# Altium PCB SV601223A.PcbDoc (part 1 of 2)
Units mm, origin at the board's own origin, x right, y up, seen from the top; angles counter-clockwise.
Board outline 162.56 x 88.9 mm, 2 copper layers (Top Layer, Bottom Layer), stack 1.554 mm thick; 111 components, 38 nets, 197 pads, 254 vias.
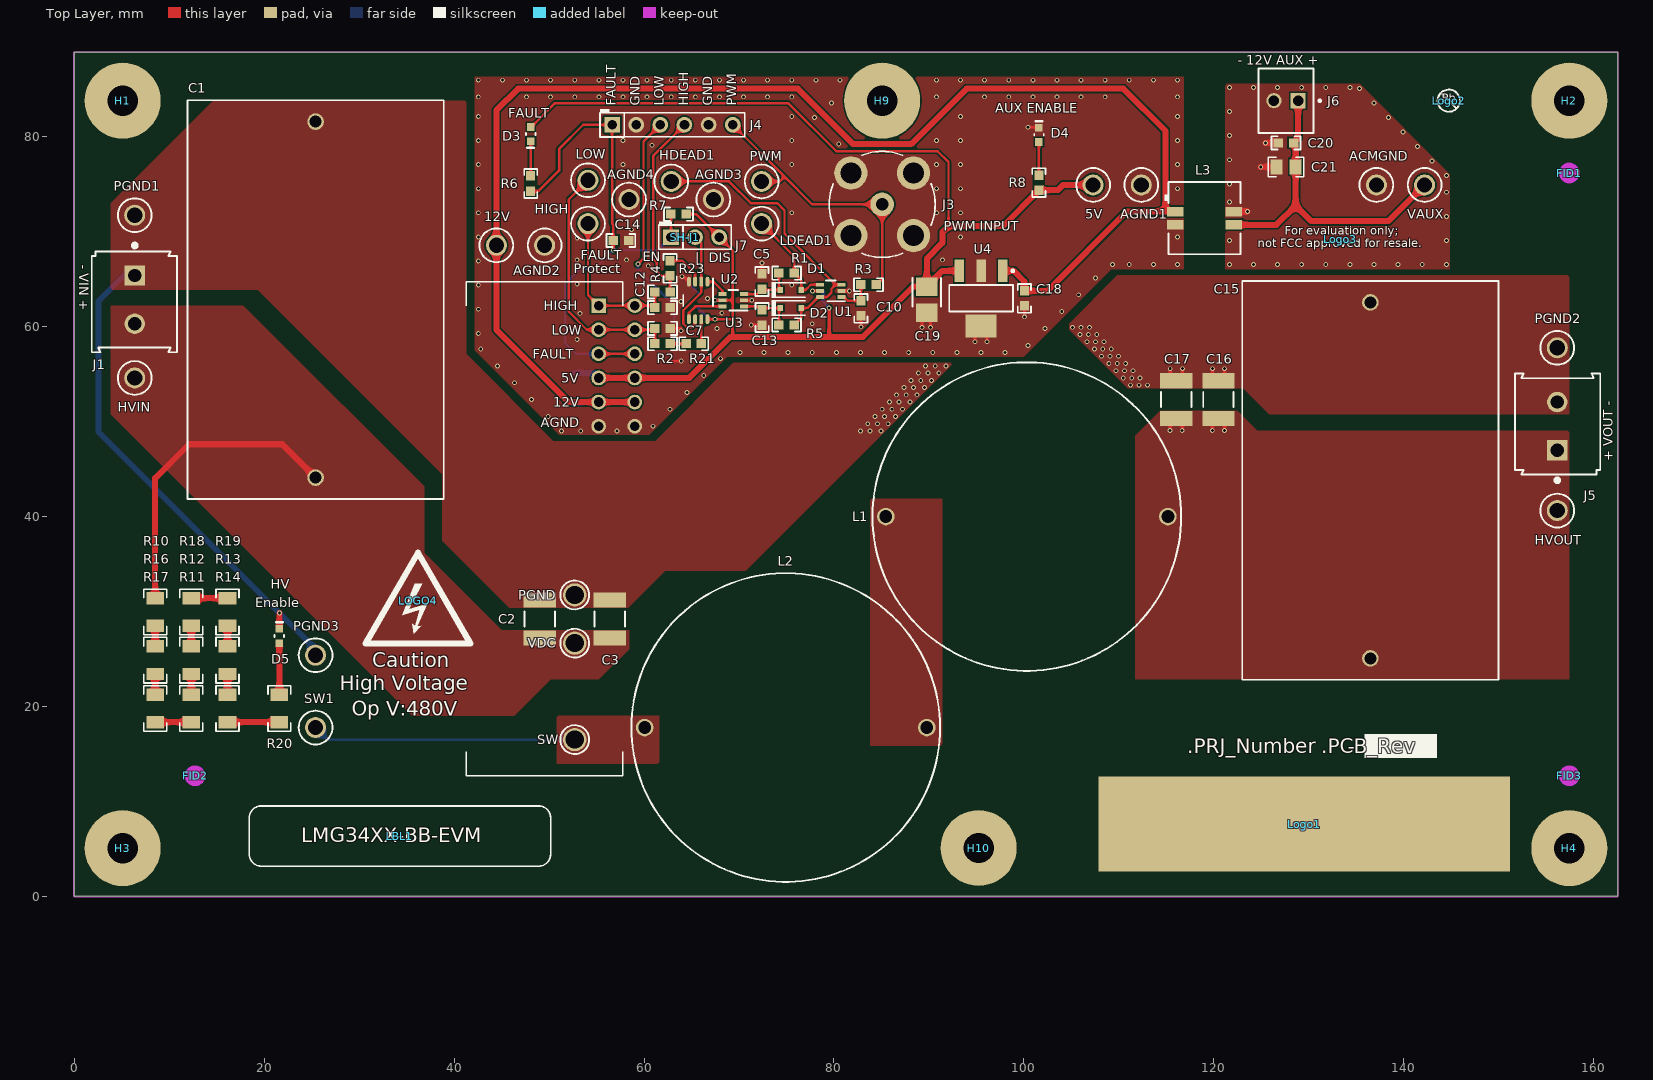
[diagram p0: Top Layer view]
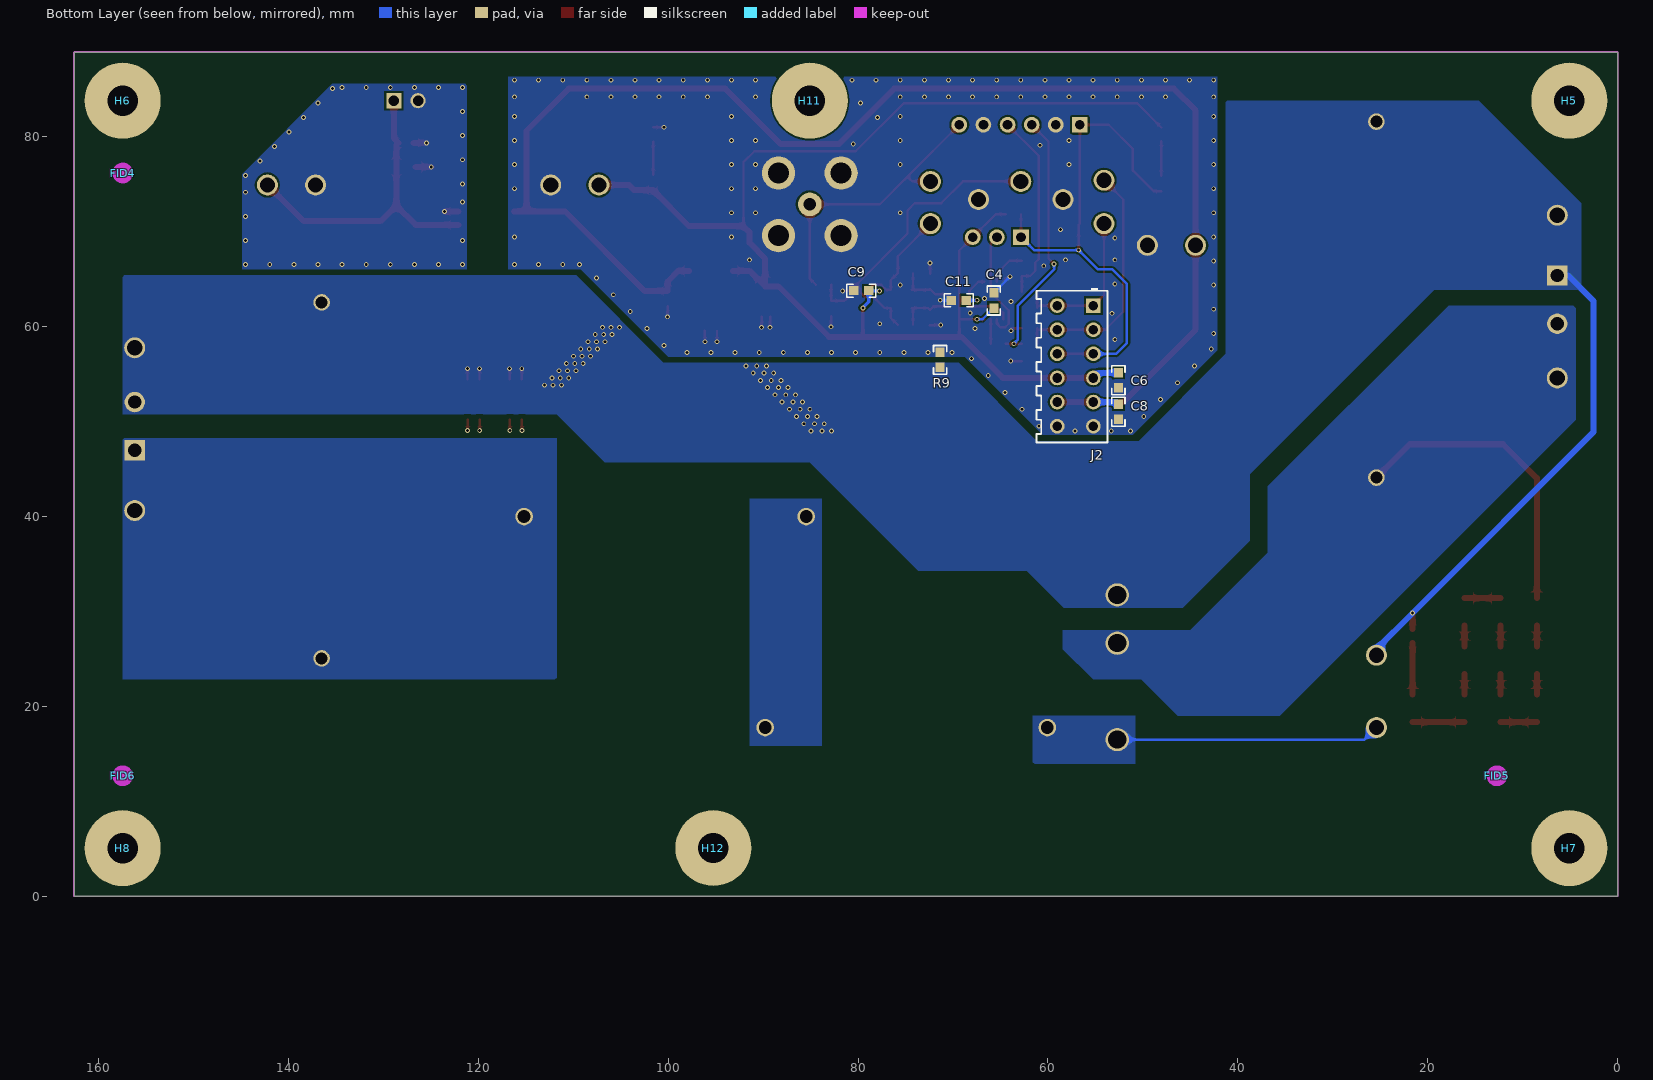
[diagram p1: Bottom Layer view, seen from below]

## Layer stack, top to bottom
Top Solder: solder mask 0.0102, Solder Resist, Dk 3.5
Top Layer: signal copper 0.0711
Dielectric1: core 1.4122, FR-4 High Tg, Dk 4.8
Bottom Layer: signal copper 0.0711
Bottom Solder: solder mask 0.0102, Solder Resist, Dk 3.5

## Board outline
0,0 162.56,0 162.56,88.9 0,88.9

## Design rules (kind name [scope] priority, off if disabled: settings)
AcuteAngle [All] p1: minimum=4.50000000000000E+0001 checktracksonly=FALSE
AssemblyTestPointUsage [All] p1: valid=2
Clearance Clearance_HV [InNetClass('HV')] p1: gap=1.524
Clearance Clearance_Keepouts [((IsTrack Or IsArc) And Not InPoly) And IsFree and IsKeepOut vs ((IsTrack Or IsArc) And Not InPoly) And IsFree and IsKeepOut] p2: gap=0
Clearance Clearance_BoardEdge_MountingHoles [OnCopper and InComponentClass('Mounting Holes') vs IsKeepOut] p3: gap=1.016
Clearance Clearance_BoardEdge [OnCopper and Not InComponentClass('Logo') and not InComponentClass('FiducialMark') and not InRegion(1000,500,4000,800) and Not IsKeepout vs IsKeepOut] p4: gap=1.905
Clearance [All] p5: gap=0.2
ComponentClearance ComponentClearance_MountingHoles_FiducialMarks [InComponentClass('Mounting Holes') vs InComponentClass('FiducialMark')] p1: gap=1.27 collisioncheckmode=3 verticalgap=0.254 showdistances=FALSE
ComponentClearance ComponentClearance_Shunt [InComponentClass('Header') vs InComponentClass('Shunt')] p2: gap=0 collisioncheckmode=3 verticalgap=0 showdistances=FALSE
ComponentClearance ComponentClearance_Logo [InComponentClass('Logo')] p3: gap=1.27 collisioncheckmode=3 verticalgap=0.254 showdistances=FALSE
ComponentClearance ComponentClearance_PowerConnector [(HasFootprint('Mill-Max_0312-0-15-15-34-27-10-0') or HasFootprint('Molex_0448120024'))] p4: gap=0 collisioncheckmode=3 verticalgap=0 showdistances=FALSE
ComponentClearance ComponentClearance_ScrewToNut [(HasFootprint('NY PMS 440 0025 PH')) vs (HasFootprint('Keystone_1902C'))] p5: gap=0.127 collisioncheckmode=3 verticalgap=0.254 showdistances=FALSE
ComponentClearance ComponentClearance_MountingHoles [InComponentClass('Mounting Holes')] p6: gap=1.27 collisioncheckmode=3 verticalgap=2540 showdistances=FALSE
ComponentClearance ComponentClearance_SmallPassives [HasFootprint('0201*') or HasFootprint('0402*') or HasFootprint('0508') or HasFootprint('0603*') or HasFootprint('0612') or HasFootprint('0805*') or HasFootprint('0815*') or HasFootprint('0830*') or HasFootprint('1206*') or HasFootprint('1210*') or HasFootprint('1808*') or HasFootprint('1812*') or HasFootprint('1825*') or HasFootprint('2010*') or HasFootprint('2220*') or HasFootprint('2225*') or HasFootprint('2512*') or HasFootprint('2728*') or HasFootprint('3518*') vs HasFootprint('0201*') or HasFootprint('0402*') or HasFootprint('0508') or HasFootprint('0603*') or HasFootprint('0612') or HasFootprint('0805*') or HasFootprint('0815*') or HasFootprint('0830*') or HasFootprint('1206*') or HasFootprint('1210*') or HasFootprint('1808*') or HasFootprint('1812*') or HasFootprint('1825*') or HasFootprint('2010*') or HasFootprint('2220*') or HasFootprint('2225*') or HasFootprint('2512*') or HasFootprint('2728*') or HasFootprint('3518*')] p7: gap=0.508 collisioncheckmode=3 verticalgap=0.254 showdistances=FALSE
ComponentClearance ComponentClearance_THtoSMT [IsThruComponent vs IsSMTComponent] p8: gap=0.4 collisioncheckmode=3 verticalgap=0.762 showdistances=FALSE
ComponentClearance ComponentClearance_THtoTH [IsThruComponent vs IsThruComponent] p9: gap=0.2 collisioncheckmode=3 verticalgap=0.762 showdistances=FALSE
ComponentClearance [All] p10: gap=0.254 collisioncheckmode=3 verticalgap=0.254 showdistances=FALSE
DiffPairsRouting [All] p1: maxlimit=2.54 minlimit=0.254 mostfreqgap=0.254 toplayer_minwidth=0.381 toplayer_maxwidth=0.381 toplayer_prefwidth=0.381 bottomlayer_minwidth=0.381 bottomlayer_maxwidth=0.381 bottomlayer_prefwidth=0.381 maxuncoupledlength=25.4
FabricationTestPointUsage TestPointUsage [All] p1: valid=2 allowmultiple=FALSE
FabricationTestpoint Testpoint [All] p1: side=3 testpointundercomponent=TRUE minsize=1.016 maxsize=2.54 preferedsize=1.524 minholesize=0 maxholesize=1.016 preferedholesize=0.813 testpointgrid=0.025 allowsidetop=TRUE allowsidebottom=TRUE usegrid=TRUE gridtolerance=0
FanoutControl Fanout_LCC [IsLCC] p1: bgadir=Out bgaviamode=Centered fanoutstyle=Auto fanoutdirection=Alternating viagrid=0.025 // Fanout_LCC (Default Rule)
FanoutControl Fanout_BGA [IsBGA] p2: bgadir=Out bgaviamode=Centered fanoutstyle=Auto fanoutdirection=Alternating viagrid=0.025 // Fanout_BGA (Default Rule)
FanoutControl Fanout_Default [All] p4: bgadir=Out bgaviamode=Centered fanoutstyle=Auto fanoutdirection=Alternating viagrid=0.025 // Fanout_Default (Default Rule)
FanoutControl Fanout_Small [(CompPinCount < 5)] p5: bgadir=Out bgaviamode=Centered fanoutstyle=Auto fanoutdirection=OutThenIn viagrid=0.025 // Fanout_Small (Default Rule)
Height [All] p1: minheight=0 maxheight=50.8 prefheight=12.7
HoleSize [All] p1: absolutevalues=TRUE maxlimit=6.375 minlimit=0.203 maxpercent=80.000 minpercent=20.000
MinimumAnnularRing MinimumAnnularRing_ThermalPadVias [IsVia and InAnyComponent] p1: minimumring=0.15
MinimumAnnularRing [All] p2: minimumring=0.076
MinimumSolderMaskSliver MinimumSolderMaskSliver_Logo [InComponentClass('Logo') vs InComponentClass('Logo')] p1: minsoldermaskwidth=0
MinimumSolderMaskSliver [All] p2: minsoldermaskwidth=0
PlaneConnect [All] p1: planeconnectstyle=Direct reliefexpansion=0.254 reliefentries=4 reliefconductorwidth=0.254 reliefairgap=0.254
PolygonConnect [All] p1: connectstyle=Direct reliefconductorwidth=0.254 reliefentries=4 polygonreliefangle="90 Angle" airgapwidth=0.254
RoutingVias ThermalPadVias [IsVia and InAnyComponent] p1: holewidth=0.2 width=0.5 viastyle="Through Hole" minholewidth=0.2 minwidth=0.5 maxholewidth=0.33 maxwidth=0.6
RoutingVias [All] p2: holewidth=0.406 width=0.864 viastyle="Through Hole" minholewidth=0.2 minwidth=0.483 maxholewidth=1.016 maxwidth=1.651
SilkToBoardRegionClearance [Not ((IsComment or IsDesignator) And (Hide <> 'False')) and not InRegion(1000,500,4000,800)] p1:
SilkToSilkClearance SilkToSilkClearance_Pb-FreeLogo [(HasFootprint('Pb-Free_Overlay_Medium') OR HasFootprint('Pb-Free_Overlay_Small')) vs (HasFootprint('Pb-Free_Overlay_Medium') OR HasFootprint('Pb-Free_Overlay_Small'))] p1: silktosilkclearance=0
SilkToSilkClearance [All] p2: silktosilkclearance=0
SilkToSolderMaskClearance "Silk to Solder Mask Opening" [All] p1: minsilkscreentomaskgap=0 clearancetoexposedcopper=FALSE
SolderMaskExpansion [All] p1: expansion=0.05
Width [All] p1: maxlimit=2.54 minlimit=0.152 preferedwidth=0.254 checkconnectedcopper=TRUE
14 further rules are at their usual default settings.

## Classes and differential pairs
component class Shunt: SH-J1
component class NoTherm: C2 C3 C16 C17
component class Label: LBL1
component class AssemblyNote: ZZ1 ZZ2 ZZ3 ZZ4
component class FiducialMark: FID1 FID2 FID3 FID4 FID5 FID6
component class EVM_Hardware: FID1 FID2 FID3 FID4 FID5 FID6 H1 H2 H3 H4 H5 H6 H7 H8 H9 H10 H11 H12 LBL1 Logo1 Logo2 Logo3 LOGO4 ZZ1 ZZ2 ZZ3 ZZ4
component class Logo: Logo1
component class "Mounting Holes": H1 H2 H3 H4 H9 H10
component class Header: J4 J7
component class MB_Schematic: 5V 12V ACMGND AGND1 AGND2 AGND3 AGND4 C1 C2 C3 C4 C5 C6 C7 C8 C9 C10 C11 C12 C13 C14 C15 C16 C17 C18 C19 C20 C21 D1 D2 D3 D4 D5 HDEAD1 HIGH HVIN HVOUT J1 J2 J3 J4 J5 J6 J7 L1 L2 L3 LDEAD1 LOW PGND PGND1 PGND2 PGND3 PWM R1 R2 R3 R4 R5 R6 R7 R8 R9 R10 R11 R12 R13 R14 R16 R17 R18 R19 R20 R21 R23 SH-J1 SW SW1 U1 U2 U3 U4 VAUX VDC
net class HV: NetC1_1 NetC15_1 NetL1_2 NetL2_2 NetR10_1 NetR11_1 NetR11_2 NetR12_1 NetR13_1 NetR13_2 NetR14_1 NetR16_1 NetR18_1

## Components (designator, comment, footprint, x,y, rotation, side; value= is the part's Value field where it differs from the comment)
5V "5005" Keystone5005 107.312,74.943 r90 top
12V "5005" Keystone5005 44.45,68.58 r90 top
ACMGND "5006" Keystone5006 137.157,74.943 r90 top
AGND1 "5006" Keystone5006 112.392,74.943 r90 top
AGND2 "5006" Keystone5006 49.53,68.58 r90 top
AGND3 "5006" Keystone5006 67.31,73.406 r90 top
AGND4 "5006" Keystone5006 58.42,73.406 r90 top
C1 "MKP1848S55010JP2C" MKP1848Sx2_4200x1800x2700 25.4,62.865 r90 top
C2 "GRM43DR72J104KW01L" 1812 49.022,29.21 r90 top
C3 "GRM43DR72J104KW01L" 1812 56.388,29.21 r90 top
C4 "C1608X7R1E105K080AB" 0603 65.71,62.772 r270 bottom
C5 "C1608C0G1H390J" 0603 72.417,64.77 r90 top
C6 "C1608X7R1E105K080AB" 0603 52.578,54.356 r270 bottom
C7 "C1608C0G1H390J" 0603 61.951,59.834 r0 top
C8 "C1608X7R1E105K080AB" 0603 52.578,51.054 r270 bottom
C9 "C1608X7R1E105K080AB" 0603 79.67,63.8 r180 bottom
C10 "C1608C0G1H390J" 0603 82.855,61.938 r270 top
C11 "C1608X7R1E105K080AB" 0603 69.403,62.794 r180 bottom
C12 "C1608C0G1H390J" 0603 61.951,62.027 r0 top
C13 "C1608C0G1H390J" 0603 72.44,60.981 r270 top
C14 "GRM1885C1E102JA01D" 0603 57.569,69.088 r0 top
C15 "MKP1848S55010JP2C" MKP1848Sx2_4200x1800x2700 136.525,43.815 r90 top
C16 "GRM43DR72J104KW01L" 1812 120.515,52.324 r90 top
C17 "GRM43DR72J104KW01L" 1812 116.07,52.324 r90 top
C18 "GRM188R71E105KA12D" 0603 100.076,62.992 r90 top
C19 "TPSB336K016R0350" 3528-21 89.789,62.865 r270 top
C20 "GRM188R71E105KA12D" 0603 127.635,79.375 r0 top
C21 "GRM219R61E106KA12D" 0805_HV 127.635,76.835 r180 top
D1 "BAT54WS-7-F" sod-323 75.465,63.881 r0 top
D2 "BAT54WS-7-F" sod-323 75.465,61.976 r0 top
D3 "LS L29K-G1J2-1-Z" "LS L29K_Red" 48.068,80.294 r270 top
D4 "LG L29K-G2J1-24-Z" "LG L29K_GREEN" 101.6,80.22 r90 top
D5 "LS L29K-G1J2-1-Z" "LS L29K_Red" 21.59,27.42 r90 top
FID1 "Fiducial" Fiducial10-20 157.48,76.2 r0 top
FID2 "Fiducial" Fiducial10-20 12.7,12.7 r0 top
FID3 "Fiducial" Fiducial10-20 157.48,12.7 r0 top
FID4 "Fiducial" Fiducial10-20 157.48,76.2 r180 bottom
FID5 "Fiducial" Fiducial10-20 12.7,12.7 r180 bottom
FID6 "Fiducial" Fiducial10-20 157.48,12.7 r180 bottom
H1 "NY PMS 440 0025 PH" "NY PMS 440 0025 PH" 5.08,83.82 r0 top locked
H2 "NY PMS 440 0025 PH" "NY PMS 440 0025 PH" 157.48,83.82 r0 top locked
H3 "NY PMS 440 0025 PH" "NY PMS 440 0025 PH" 5.08,5.08 r0 top locked
H4 "NY PMS 440 0025 PH" "NY PMS 440 0025 PH" 157.48,5.08 r0 top locked
H5 "1902C" Keystone_1902C#1 5.08,83.82 r180 bottom locked
H6 "1902C" Keystone_1902C#1 157.48,83.82 r180 bottom locked
H7 "1902C" Keystone_1902C#1 5.08,5.08 r180 bottom locked
H8 "1902C" Keystone_1902C#1 157.48,5.08 r180 bottom locked
H9 "NY PMS 440 0025 PH" "NY PMS 440 0025 PH" 85.09,83.82 r90 top
H10 "NY PMS 440 0025 PH" "NY PMS 440 0025 PH" 95.25,5.086 r90 top
H11 "1902C" Keystone_1902C#2 85.09,83.814 r180 bottom
H12 "1902C" Keystone_1902C#2 95.25,5.086 r180 bottom
HDEAD1 "5012" Keystone5012 62.865,75.311 r180 top
HIGH "5012" Keystone5012 54.102,70.866 r0 top
HVIN "5005" Keystone5005 6.35,54.61 r0 top
HVOUT "5005" Keystone5005 156.21,40.64 r180 top
J1 "282841-2" TEC_282841-2 6.35,62.865 r270 top
J2 "0448120024" Molex_0448120024 57.125,55.88 r270 bottom
J3 "112404" Amphenol_112404 85.09,72.898 r0 top
J4 "TSW-106-07-G-S" TSW-106-07-G-S 62.992,81.28 r0 top
J5 "282841-2" TEC_282841-2 156.21,49.53 r90 top
J6 "282834-2" TEC_282834-2 127.635,83.82 r180 top
J7 "TSW-103-07-G-S" TSW-103-07-G-S 65.38,69.444 r0 top
L1 "2300HT-151-H-RC" 2300HT-H 100.33,40.005 r180 top
L2 "2300HT-151-H-RC" 2300HT-H 74.93,17.78 r180 top
L3 "DRQ73-470-R" DRQ73 119.036,71.444 r0 top
LBL1 "Size: 1.25\" x 0.25\"" Label_1250x250 34.29,6.35 r0 top
LDEAD1 "5012" Keystone5012 72.39,70.866 r180 top
Logo1 "Texas Instruments" TI_Stacked_SolderMask_Medium 129.54,7.62 r0 top
Logo2 "Pb-Free Symbol" Pb-Free_Overlay_Small 144.78,83.82 r0 top
Logo3 "FCC disclaimer" FCC_disclaimer_stacked 133.35,69.215 r0 top
LOGO4 "DANGER HIGH VOLTAGE" IEC_HighVoltage_Medium 36.195,31.115 r0 top
LOW "5012" Keystone5012 54.102,75.438 r0 top
PGND "Suggest using a net name here" Mill-Max_0312-0-15-15-34-27-10-0 52.705,31.75 r90 top
PGND1 "5006" Keystone5006 6.35,71.755 r0 top
PGND2 "5006" Keystone5006 156.21,57.785 r0 top
PGND3 "5006" Keystone5006 25.4,25.4 r0 top
PWM "5012" Keystone5012 72.39,75.311 r0 top
R1 "RC0603FR-071K2L" 0603 75.02,65.659 r180 top
R2 "CRCW06030000Z0EA" 0603 61.951,58.217 r0 top
R3 "CRCW06030000Z0EA" 0603 83.655,64.435 r0 top
R4 "CRCW06030000Z0EA" 0603 61.951,63.678 r180 top
R5 "RC0603FR-071K2L" 0603 75.02,60.198 r180 top
R6 "CRCW06031K60JNEA" 0603 48.068,75.09 r90 top
R7 "ERJ-3EKF1002V" 0603 63.64,71.869 r0 top
R8 "CRCW06031K60JNEA" 0603 101.6,75.19 r270 top
R9 "CRCW06030000Z0EA" 0603 71.374,56.515 r270 bottom
R10 "CRCW120630K0JNEA" 1206 8.505,29.96 r90 top
R11 "CRCW120630K0JNEA" 1206 12.315,19.8 r90 top
R12 "CRCW120630K0JNEA" 1206 12.315,24.88 r270 top
R13 "CRCW120630K0JNEA" 1206 16.125,24.88 r270 top
R14 "CRCW120630K0JNEA" 1206 16.125,19.8 r90 top
R16 "CRCW120630K0JNEA" 1206 8.505,24.88 r90 top
R17 "CRCW120630K0JNEA" 1206 8.505,19.8 r270 top
R18 "CRCW120630K0JNEA" 1206 12.315,29.96 r270 top
R19 "CRCW120630K0JNEA" 1206 16.125,29.96 r270 top
R20 "CRCW120630K0JNEA" 1206 21.59,19.8 r270 top
R21 "CRCW06030000Z0EA" 0603 65.253,58.217 r0 top
R23 "CRCW06030000Z0EA" 0603 62.751,66.154 r90 top
SH-J1 "969102-0000-DA" SNT-100-BK-G 64.346,69.444 r180 top
SW "Suggest using a net name here" Mill-Max_0312-0-15-15-34-27-10-0 52.705,16.51 r90 top
SW1 "5005" Keystone5005 25.4,17.78 r0 top
U1 "SN74LVC2G14DCKR" DCK0006A_N 79.688,63.785 r180 top
U2 "SN74LVC2G08IDCTRQ1" DCT0008A_N 65.71,62.772 r270 top
U3 "SN74LVC2G14DCKR" DCK0006A_N 69.403,62.794 r180 top
U4 "LM2940IMP-5.0/NOPB" MP04A_N 95.504,62.992 r270 top
VAUX "5005" Keystone5005 142.237,74.943 r90 top
VDC "Suggest using a net name here" Mill-Max_0312-0-15-15-34-27-10-0 52.705,26.67 r90 top
ZZ1 "This Assembly Note is for PCB labels only" AssemblyNoteLabel 2.54,121.92 r0 top
ZZ2 "These assemblies are ESD sensitive, ESD precautions shall be observed." AssemblyNote 2.54,119.38 r0 top
ZZ3 "These assemblies must be clean and free from flux and all contaminants. Use of no clean flux is not acceptable." AssemblyNote 2.54,116.84 r0 top
ZZ4 "These assemblies must comply with workmanship standards IPC-A-610 Class 2, unless otherwise specified." AssemblyNote 2.54,114.3 r0 top

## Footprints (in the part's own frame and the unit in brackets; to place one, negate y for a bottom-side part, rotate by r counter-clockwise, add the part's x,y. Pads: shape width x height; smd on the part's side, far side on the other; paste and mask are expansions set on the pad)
0603 [mm] "0603 from SM-752 data"
  rect 1x0.95 smd: 1(-0.8,0) 2(0.8,0)
  silkscreen extent -1.52,-0.69 1.52,0.69, body extent -0.87,-0.47 0.87,0.47, height 1
0805_HV [mil] "0805 with 30mil clearance between pads"
  rect 50x63 smd: 1(-40,0) 2(40,0)
  silkscreen extent -74,-40 74,40, body extent -43,-29 43,29, height 57
1206 [mm] "1206 from SM-752 data"
  rect 1.3x1.85 smd: 1(-1.45,0) 2(1.45,0)
  silkscreen extent -2.4,-1.21 2.4,1.21, body extent -1.7,-0.9 1.7,0.9, height 1.35
1812 [mm]
  rect 1.6x3.4 smd: 1(-2,0) 2(2,0)
  silkscreen extent -0.8,-1.6 0.8,1.6, body extent -2.4,-1.7 2.4,1.7, height 1.35
2300HT-H [mm] "TH, 2-Leads, Dia 1280mil, Lead Spacing 1170mil"
  round 1.85 hole 1.35: 1(-14.859,0) 2(14.859,0)
  silkscreen extent -16.26,-16.25 16.26,16.25, body extent -16.79,-16.79 16.79,16.79, height 16.73
3528-21 [mm] "Medium Density IPC, based on SM-782 section 8.4"
  rect 1.95x2.25 smd: 1(-1.375,0) 2(1.375,0)
  silkscreen extent -2.29,-1.5 0.76,1.5, body extent -1.85,-1.5 1.85,1.5, height 2.1
Amphenol_112404 [mm] "BNC footprint, pins compatible with Amp 5413631-2"
  round 2.5 hole 1.3: 1(0,0)
  round 3.5 hole 2.2: 2(-3.3,3.3) 3(3.3,3.3) 4(3.3,-3.3) 5(-3.3,-3.3)
  silkscreen extent -5.59,-5.59 5.59,5.59, body extent -5.5,-5.5 5.5,5.5, height 13.7
AssemblyNote [mm] "Assembly Note"
AssemblyNoteLabel [mm] "Assembly Note for PCB Labels"
DCK0006A_N [mm] "SOT23, 6-Leads, Body 2x1.3mm, Pitch 0.65mm, Lead Span 2.1mm, IPC Medium Density"
  rrect25% 0.85x0.4 smd: 1(-1.125,0.65) 2(-1.125,0) 3(-1.125,-0.65) 4(1.125,-0.65) 5(1.125,0) 6(1.125,0.65)
  silkscreen extent -1.5,-1.09 0.51,1.09, body extent -1.14,-1 1.14,1, height 0.95
DCT0008A_N [mm] "TSOP, 8-Leads, Body 3x2.8mm, Pitch 0.65mm, IPC Medium Density"
  oval 1.05x0.4 smd: 1(-1.975,0.975) 2(-1.975,0.325) 3(-1.975,-0.325) 4(-1.975,-0.975) 5(1.975,-0.975) 6(1.975,-0.325) 7(1.975,0.325) 8(1.975,0.975)
  silkscreen extent -2.32,-1.57 0.6,1.58, body extent -2.01,-1.47 2.01,1.48, height 1.3
DRQ73 [mm] "SMD, 4-Leads, Body 7.6x7.6mm"
  rect 1.73x1 smd: 1(-3.085,0.7) 2(-3.085,-0.7) 3(3.085,-0.7) 4(3.085,0.7)
  silkscreen extent -4.2,-3.8 3.8,3.8, body extent -4.01,-3.8 3.93,3.8, height 3.4
FCC_disclaimer_stacked [mm]
Fiducial10-20 [mm]
  round 1 smd mask+0.5: 1(0,0)
  Top Layer keep-out circle w1.178: c0,0 r0.5
IEC_HighVoltage_Medium [mm]
  silkscreen extent -5.51,-4.46 5.51,5.09
Keystone5005 [mil] "Keystone Compact loops"
  round 87 hole 63: 1(0,0)
  silkscreen extent -70,-70 70,70, body extent -63,-63 62,63, height 225
Keystone5006 [mil] "Keystone Compact loops"
  round 87 hole 63: 1(0,0)
  silkscreen extent -70,-70 70,70, body extent -63,-63 62,63, height 225
Keystone5012 [mil] "Keystone Multipurpose loops"
  round 87 hole 63: 1(0,0)
  silkscreen extent -70,-70 70,70, body extent -63,-63 63,62, height 319
Keystone_1902C#1 [mm] "Hex Standoff, 4-40 threaded, nylon"
  body extent -3.68,-3.2 3.71,3.2, height 12.73
Keystone_1902C#2 [mm] "Hex Standoff, 4-40 threaded, nylon"
  round 0.025 on Mech4: 0(0,0)
  body extent -3.68,-3.2 3.71,3.2, height 12.73
Label_1250x250 [mil] "Thermal Transfer Labels"
  round 1 on Mech13: 0(0,0)
  silkscreen extent -625,-125 625,125, body extent -625,-125 625,125, height 1
"LG L29K_GREEN" [mm] "OSRAM"
  rect 0.8x0.8 smd paste-0.4: 1(-0.75,0) 2(0.75,0)
  silkscreen extent -0.1,-0.5 1.45,0.5, body extent -0.9,-0.45 0.9,0.45, height 0.67
"LS L29K_Red" [mm] "SMD, 2-Leads, Body 1.3x0.8mm"
  rect 0.8x0.8 smd paste-0.4: 1(-0.75,0) 2(0.75,0)
  silkscreen extent -0.1,-0.5 1.45,0.5, body extent -0.9,-0.45 0.9,0.45, height 0.67
Mill-Max_0312-0-15-15-34-27-10-0 [mm] "Pin Receptacle, .032-.046\" .075\" Dia, Gold, TH"
  round 2.45 hole 1.905: 1(0,0)
  silkscreen extent -1.52,-1.52 1.52,1.52, body extent -1.15,-1.15 1.16,1.15, height 0.46
MKP1848Sx2_4200x1800x2700 [mm] "TH, 2-Leads, Body 42x27mm"
  round 1.75 hole 1.25: 1(-18.75,0) 2(18.75,0)
  silkscreen extent -21,-13.5 21,13.5, body extent -21,-13.5 21,13.5, height 18
Molex_0448120024 [mm] "Receptacle, 2.54mm, 6x1, TH"
  round 1.55 hole 1.02: 1(-6.35,-1.905) 2(-3.81,-1.905) 2(-3.81,1.905) 3(-1.27,-1.905) 3(-1.27,1.905) 4(1.27,-1.905) 4(1.27,1.905) 5(3.81,-1.905) 5(3.81,1.905) 6(6.35,-1.905) 6(6.35,1.905)
  rect 1.55x1.55 hole 1.02: 1(-6.35,1.905)
  silkscreen extent -8.2,-4.09 8.08,3.4, body extent -7.92,-4.09 8.08,3.4, height 4.5
MP04A_N [mm] "SOT223, 4-Leads, Body 6.5x3.5mm, Pitch 2.3mm, Lead Span 7mm, IPC Medium Density"
  rect 2.4x1 smd: 1(-2.9,2.3) 2(-2.9,0) 3(-2.9,-2.3)
  rect 2.4x3.3 smd: 4(2.9,0)
  silkscreen extent -3.02,-3.35 1.4,3.48, body extent -1.85,-3.35 1.85,3.35, height 1.8
"NY PMS 440 0025 PH" [mm] "4-40 nylon screw and mounting hole"
  round 8 hole 3.2: 1(0,0)
  body extent -3.3,-3.3 3.3,3.3, height 2.69
Pb-Free_Overlay_Small [mm]
  silkscreen extent -1.16,-1.17 1.17,1.17
SNT-100-BK-G [mil] "Samtec STEP model"
  round 1 on Mech3: 0(0,0)
  body extent -100,-50 100,50, height 344
sod-323 [mm] "NXP recommended land pattern"
  rect 0.6x0.6 smd paste-0.05: 1(-1.1,0) 2(1.1,0)
  silkscreen extent -2.06,-0.86 1.53,0.86, body extent -1.3,-0.67 1.3,0.68, height 1.1
TEC_282834-2 [mm] "TEC"
  rect 1.6x1.6 hole 1.1: 1(-1.27,0)
  round 1.6 hole 1.1: 2(1.27,0)
  silkscreen extent -3.66,-3.4 2.9,3.4, body extent -2.77,-3.25 2.77,3.25, height 10.01
TEC_282841-2 [mm] "TE Connectivity"
  rect 2.15x2.15 hole 1.4: 1(-2.54,0)
  round 2.15 hole 1.4: 2(2.54,0)
  silkscreen extent -5.9,-4.52 5.55,4.47, body extent -5.08,-4.52 5.58,4.48, height 15.2
TI_Stacked_SolderMask_Medium [mil]
  rect 1706x392 smd paste-196 mask-196: 0(0,0)
TSW-103-07-G-S [mm] "Samtec 100mil, 1x3, 230 mil above insulator"
  rect 1.65x1.65 hole 1.016: 1(-2.54,0)
  round 1.65 hole 1.016: 2(0,0) 3(2.54,0)
  silkscreen extent -3.81,-1.27 3.81,1.65, body extent -3.81,-1.27 3.81,1.27, height 8.38
TSW-106-07-G-S [mm] "Samtec 100mil, 1x6, 230 mil above insulator"
  rrect6% 1.65x1.65 hole 1.016: 1(-6.35,0)
  round 1.65 hole 1.016: 2(-3.81,0) 3(-1.27,0) 4(1.27,0) 5(3.81,0) 6(6.35,0)
  silkscreen extent -7.62,-1.27 7.62,1.65, body extent -7.62,-1.27 7.62,1.27, height 8.38

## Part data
5V 12V HVIN HVOUT SW1 VAUX: "Test Point, Compact, Red, TH"
ACMGND AGND1 AGND2 AGND3 AGND4 PGND1 PGND2 PGND3: "Test Point, Compact, Black, TH"
C1 C15: "CAP, Film, 5 µF, 1000 V, +/- 5%, 0.016 ohm, TH"
C2 C3 C16 C17: "CAP, CERM, 0.1uF, 630V, +/-10%, X7R, 1812"
C4 C6 C8 C9 C11 C18 C20: "CAP, CERM, 1 µF, 25 V, +/- 10%, X7R, 0603"
C5 C7 C10 C12 C13: "CAP, CERM, 39 pF, 50 V, +/- 5%, C0G/NP0, 0603"
C14: "CAP, CERM, 1000 pF, 25 V, +/- 5%, C0G/NP0, 0603"
C19: "CAP, TA, 33 µF, 16 V, +/- 10%, 0.35 ohm, SMD"
C21: "CAP, CERM, 10 µF, 25 V, +/- 10%, X5R, 0805"
D1 D2: "Diode, Schottky, 30 V, 0.2 A, SOD-323"
D3 D5: "LED, Red, SMD"
D4: "LED, Green, SMD"
FID1 FID2 FID3 FID4 FID5 FID6: "Fiducial mark.  There is nothing to buy or mount."
H1 H2 H3 H4 H9 H10: "Machine Screw, Round, #4-40 x 1/4, Nylon, Philips panhead"
H5 H6 H7 H8 H11 H12: "Standoff, Hex, 0.5\"L #4-40 Nylon"
HDEAD1 HIGH LDEAD1 LOW PWM: "Test Point, Multipurpose, White, TH"
J1 J5: "Terminal Block, 2x1, 5.08mm, TH"
J2: "Receptacle, 2.54mm, 6x1, Gold, TH"
J3: "Connector, TH, BNC"
J4: "Header, 100mil, 6x1, Gold, TH"
J6: "Terminal Block, 2x1, 2.54mm, TH"
J7: "Header, 100mil, 3x1, Gold, TH"
L1 L2: "Inductor, Toroid, 150 µH, 7.5 A, 0.05 ohm, TH"
L3: "Coupled inductor, 47 µH, 1.14 A, 0.241 ohm, +/- 20%, SMD"
LBL1: library part THT-13-457-10, "Thermal Transfer Printable Labels, 1.250\" W x 0.250\" H - 10,000 per roll"
Logo1: library part TI_Logo, "Texas Instrument Corporate Signature"
Logo2: library part Pb-Free
Logo3: library part FCC_disclaimer, "FCC_disclaimer"
LOGO4: library part IEC_HighVoltage, "IEC 61010-1 High Voltage Warning"
PGND SW VDC: library part 0312-0-15-15-34-27-10-0, "Pin Receptacle, .032-.046\" .075\" Dia, Gold, TH"
R1 R5: "RES, 1.20 k, 1%, 0.1 W, 0603"
R2 R3 R4 R9 R21 R23: "RES, 0, 5%, 0.1 W, 0603"
R6 R8: "RES, 1.6 k, 5%, 0.1 W, 0603"
R7: "RES, 10.0 k, 1%, 0.1 W, 0603"
R10 R11 R12 R13 R14 R16 R17 R18 R19 R20: "RES, 30 k, 5%, 0.25 W, 1206"
SH-J1: "Shunt, 100mil, Gold plated, Black"
U1 U3: "Dual Schmitt-Trigger Inverter, DCK0006A"
U2: "DUAL 2-INPUT POSITIVE-AND GATE, DCT0008A"
U4: "1A Low Dropout Regulator, 4-pin SOT-223, Pb-Free"
ZZ1: library part AssemblyNoteLabel
ZZ2 ZZ3 ZZ4: library part AssemblyNote

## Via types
v1: diameter 0.508, hole 0.305, Top Layer to Bottom Layer, 254 vias

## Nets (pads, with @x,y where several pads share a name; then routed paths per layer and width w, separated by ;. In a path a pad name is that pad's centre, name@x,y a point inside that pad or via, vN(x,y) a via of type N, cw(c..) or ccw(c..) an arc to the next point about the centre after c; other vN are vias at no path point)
5V: 5V.1 C4.2 C6.1 C9.2 C11.2 C19.1 D3.1 J2.4 J7.3 R7.2 R8.2 U1.5 U2.8 U3.5 U4.3 | length 155
  Top Layer w0.254: D3.1@48.068,80.995 50.639,83.566 75.184,83.566 80.264,78.486 90.932,78.486 92.075,77.343 92.075,70.612 ; R7.2@64.44,71.869 65.494,71.869 J7.3@67.92,69.444 69.342,68.021 69.342,62.794 ; U2.8@66.685,60.797 v1(67.469,60.797) 69.296,60.797 ; v1(67.46,62.794) U3.5@68.278,62.794 69.342,62.794 ; 69.342,58.928 69.342,62.794 ; v1(77.745,63.785) U1.5@78.563,63.785
  Top Layer w0.381: 79.502,58.928 v1(79.502,61.992)
  Top Layer w0.635: J2.4@55.22,54.61 J2.4@59.03,54.61 64.77,54.61 69.088,58.928 69.342,58.928 79.502,58.928 83.058,58.928 88.37,64.24 C19.1@89.789,64.24 ; U4.3@93.204,65.892 91.441,65.892 C19.1@89.789,64.24 ; 5V.1@107.312,74.943 104.153,74.943 103.6,74.39 R8.2@101.6,74.39 97.822,70.612 92.075,70.612 91.44,69.977 91.44,68.834 89.789,67.183 C19.1@89.789,64.24
  Bottom Layer w0.254: J2.4@55.22,55.118 J2.4@55.41,55.118 ; C4.2@65.71,61.972 66.885,60.797 v1(67.469,60.797) ; v1(67.46,62.794) C11.2@68.603,62.794 ; v1(77.745,63.785) 78.855,63.785 C9.2@78.87,63.8
  Bottom Layer w0.381: C9.2@78.87,63.8 78.87,62.624 v1(79.502,61.992)
  Bottom Layer w0.635: C6.1@52.578,55.156 54.699,55.156 J2.4@55.245,54.61
12V: 12V.1 C8.1 C18.2 J2.5 L3.1 U4.1 | length 153.6
  Top Layer w0.635: J2.5@59.055,52.07 52.07,52.07 44.45,59.69 12V.1@44.45,68.58 44.45,82.804 46.736,85.09 76.2,85.09 82.042,79.248 88.138,79.248 93.98,85.09 110.49,85.09 114.935,80.645 114.935,72.144 ; U4.1@97.804,65.892 98.954,65.892 100.076,64.77 C18.2@100.076,63.792 102.519,63.792 110.871,72.144 114.935,72.144 ; L3.1@116.244,72.144 114.935,72.144
  Bottom Layer w0.635: C8.1@52.578,51.854 52.794,52.07 J2.5@55.245,52.07
AGND: AGND1.1 AGND2.1 AGND3.1 AGND4.1 C4.1 C5.2 C6.2 C7.2 C8.2 C9.1 C10.2 C11.1 C12.2 C13.2 C14.2 C18.1 C19.2 D4.2 J2.6 J3.2 J3.3 J3.4 J3.5 J4.2 J4.5 L3.2 R9.1 U1.2 U2.4 U3.2 U4.2 U4.4 | length 18.7
  Top Layer w0.254: C7.2@62.751,59.834 63.894,59.834 ; 62.776,56.388 v1(63.919,56.388) ; v1(64.008,65.278) 64.204,65.278 64.712,64.77 U2.4@64.735,64.747 ; U3.2@70.528,62.794 v1(71.346,62.794) ; v1(71.297,60.181) C13.2@72.44,60.181 ; C5.2@72.417,65.57 v1(72.417,66.713) ; U1.2@80.813,63.785 v1(81.631,63.785) ; v1(82.855,59.995) C10.2@82.855,61.138 ; v1(89.281,59.944) C19.2@89.281,61.087 ; v1(90.17,59.944) C19.2@90.17,61.087 ; v1(94.869,58.42) U4.4@94.869,59.563 ; v1(96.139,58.42) U4.4@96.139,59.563 ; v1(100.076,61.049) C18.1@100.076,62.192 ; v1(100.457,81.02) D4.2@101.6,81.02
  Bottom Layer w0.254: v1(64.008,65.278) 64.008,65.274 64.512,64.77 64.535,64.747 C4.1@65.71,63.572 ; C11.1@70.203,62.794 v1(71.346,62.794)
  other v1: 51.308,49.022 53.34,49.022 57.15,49.022 60.96,49.53 49.911,50.546 62.738,51.308 48.133,52.324 64.516,53.086 46.355,54.102 66.294,54.864 44.577,55.88 68.072,56.642 70.104,57.277 72.644,57.277 75.184,57.277 77.724,57.277 80.264,57.277 82.804,57.277 85.344,57.277 87.884,57.277 90.424,57.277 92.964,57.277 95.504,57.277 98.044,57.277 42.799,57.658 100.457,58.039 52.959,58.674 42.545,59.309 63.894,59.58 67.691,59.817 102.235,59.817 77.724,60.325 53.264,61.417 68.199,61.468 104.013,61.595 42.545,61.849 63.894,62.662 66.675,62.992 105.791,63.373 42.545,64.389 75.565,64.389 52.959,64.516 107.569,65.151 60.452,66.421 109.347,66.548 111.125,66.548 113.665,66.548 116.205,66.548 42.545,66.929 52.959,67.056 58.166,67.056 91.44,67.056 52.959,69.342 42.545,69.469 93.345,69.469 116.205,69.469 58.674,70.231 42.545,72.009 75.565,72.009 90.805,72.009 93.345,72.009 42.545,74.549 90.805,74.549 93.345,74.549 116.205,74.549 42.545,77.089 57.785,77.089 75.565,77.089 90.805,77.089 93.345,77.089 116.205,77.089 60.833,79.121 80.518,79.248 42.545,79.629 57.785,79.629 75.565,79.629 90.805,79.629 93.345,79.629 116.205,79.629 77.978,82.042 42.545,82.169 75.565,82.169 93.345,82.169 116.205,82.169 79.756,83.566 42.545,84.226 47.625,84.226 50.165,84.226 52.705,84.226 55.245,84.226 57.785,84.226 60.325,84.226 62.865,84.226 65.405,84.226 67.945,84.226 70.485,84.226 73.025,84.226 75.565,84.226 90.805,84.226 95.885,84.226 98.425,84.226 100.965,84.226 103.505,84.226 106.045,84.226 108.585,84.226 116.205,84.226 42.545,85.979 45.085,85.979 47.625,85.979 50.165,85.979 52.705,85.979 55.245,85.979 57.785,85.979 60.325,85.979 62.865,85.979 65.405,85.979 67.945,85.979 70.485,85.979 73.025,85.979 75.565,85.979 78.105,85.979 80.645,85.979 90.805,85.979 93.345,85.979 95.885,85.979 98.425,85.979 100.965,85.979 103.505,85.979 106.045,85.979 108.585,85.979 111.125,85.979 113.665,85.979 116.205,85.979
FAULT: C14.1 J2.3 J4.1 J7.1 R6.1 R7.1 | length 55.7
  Top Layer w0.254: R6.1@48.068,74.29 48.89,74.29 51.054,76.454 51.054,78.74 53.594,81.28 J4.1@56.642,81.28 56.642,70.866 56.769,70.739 v1(56.769,68.072) ; J2.3@55.22,57.15 J2.3@59.03,57.15 ; J7.1@62.84,69.444 R7.1@62.84,71.869
  Bottom Layer w0.254: J2.3@55.22,57.15 52.832,57.15 51.689,58.293 51.689,64.516 53.213,66.04 54.737,66.04 v1(56.769,68.072) 61.468,68.072 J7.1@62.84,69.444
HIGH: C12.1 HIGH.1 J2.1 R4.2 | length 16.8
  Top Layer w0.254: HIGH.1@54.102,70.866 54.102,63.348 J2.1@55.22,62.23 J2.1@59.03,62.23 60.947,62.23 C12.1@61.151,62.027 R4.2@61.151,63.678
HIGH_2: J4.4 R4.1 R23.1 | length 20.2
  Top Layer w0.254: R4.1@62.751,63.678 R23.1@62.751,65.354 61.871,65.354 61.341,65.884 61.341,66.777 60.96,67.158 60.96,77.978 J4.4@64.262,81.28
LOW: C7.1 J2.2 LOW.1 R2.1 | length 26.2
  Top Layer w0.254: LOW.1@54.102,75.438 52.07,73.406 52.07,61.595 53.975,59.69 J2.2@55.22,59.69 J2.2@59.03,59.69 61.006,59.69 C7.1@61.151,59.834 R2.1@61.151,58.217
LOW_2: J4.3 R2.2 R21.1 | length 27.5
  Top Layer w0.254: v1(59.36,66.599) 59.944,67.183 59.944,79.502 J4.3@61.722,81.28 ; R2.2@62.751,58.217 v1(63.602,58.217) R21.1@64.453,58.217
  Bottom Layer w0.254: v1(59.36,66.599) 59.36,66.04 63.17,62.23 63.17,58.649 v1(63.602,58.217)
NetACMGND_1: ACMGND.1 C20.1 C21.2 J6.2 L3.4 | length 4.5
  Top Layer w0.635: L3.4@122.121,72.144 v1(123.571,72.144) ; v1(124.968,76.835) C21.2@126.619,76.835 ; v1(125.476,79.375) C20.1@126.835,79.375
  other v1: 121.666,66.548 124.206,66.548 126.746,66.548 129.286,66.548 131.826,66.548 134.366,66.548 136.906,66.548 139.446,66.548 141.986,66.548 144.526,66.548 121.666,69.088 144.526,69.088 144.526,71.628 121.666,73.152 144.526,74.168 121.666,75.057 144.526,75.946 143.002,77.47 121.666,77.597 141.478,78.994 121.666,80.137 139.954,80.518 138.43,82.042 121.666,82.677 136.906,83.566 135.382,85.09 121.666,85.217 124.206,85.217 126.746,85.217 129.286,85.217 131.826,85.217 134.366,85.217
NetC1_1: C1.1 C2.1 C3.1 HVIN.1 J1.2 R10.2 VDC.1 | length 32.5
  Top Layer w0.635: R10.2@8.505,31.41 8.505,44.065 12.065,47.625 21.89,47.625 C1.1@25.4,44.115
NetC5_1: C5.1 D1.1 R1.2 U3.3 | length 5.7
  Top Layer w0.254: U3.3@70.528,63.444 71.891,63.444 C5.1@72.417,63.97 72.506,63.881 D1.1@74.365,63.881 ; D1.1@74.22,64.026 R1.2@74.22,65.659
NetC10_1: C10.1 R3.1 U1.1 | length 3.9
  Top Layer w0.254: U1.1@80.813,63.135 81.038,63.135 81.435,62.738 C10.1@82.855,62.738 R3.1@82.855,64.435
NetC13_1: C13.1 D2.1 R5.2 U3.1 | length 5.9
  Top Layer w0.254: U3.1@70.528,62.144 72.076,62.144 C13.1@72.44,61.781 72.635,61.976 D2.1@74.365,61.976 74.22,61.831 R5.2@74.22,60.198
NetC15_1: C15.1 C16.1 C17.1 HVOUT.1 J5.1 L1.1 | length 4.6
  Top Layer w0.254: v1(115.427,49.062) C17.1@115.427,50.205 ; v1(116.697,49.062) C17.1@116.697,50.205 ; v1(119.872,49.062) C16.1@119.872,50.205 ; v1(121.142,49.062) C16.1@121.142,50.205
